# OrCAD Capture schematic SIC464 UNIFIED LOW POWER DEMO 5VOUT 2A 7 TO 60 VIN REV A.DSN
size B; title: SIC464 Demo Low Power Unified Board 7 to 60Vin 5Vout 2A 500K; rev: A
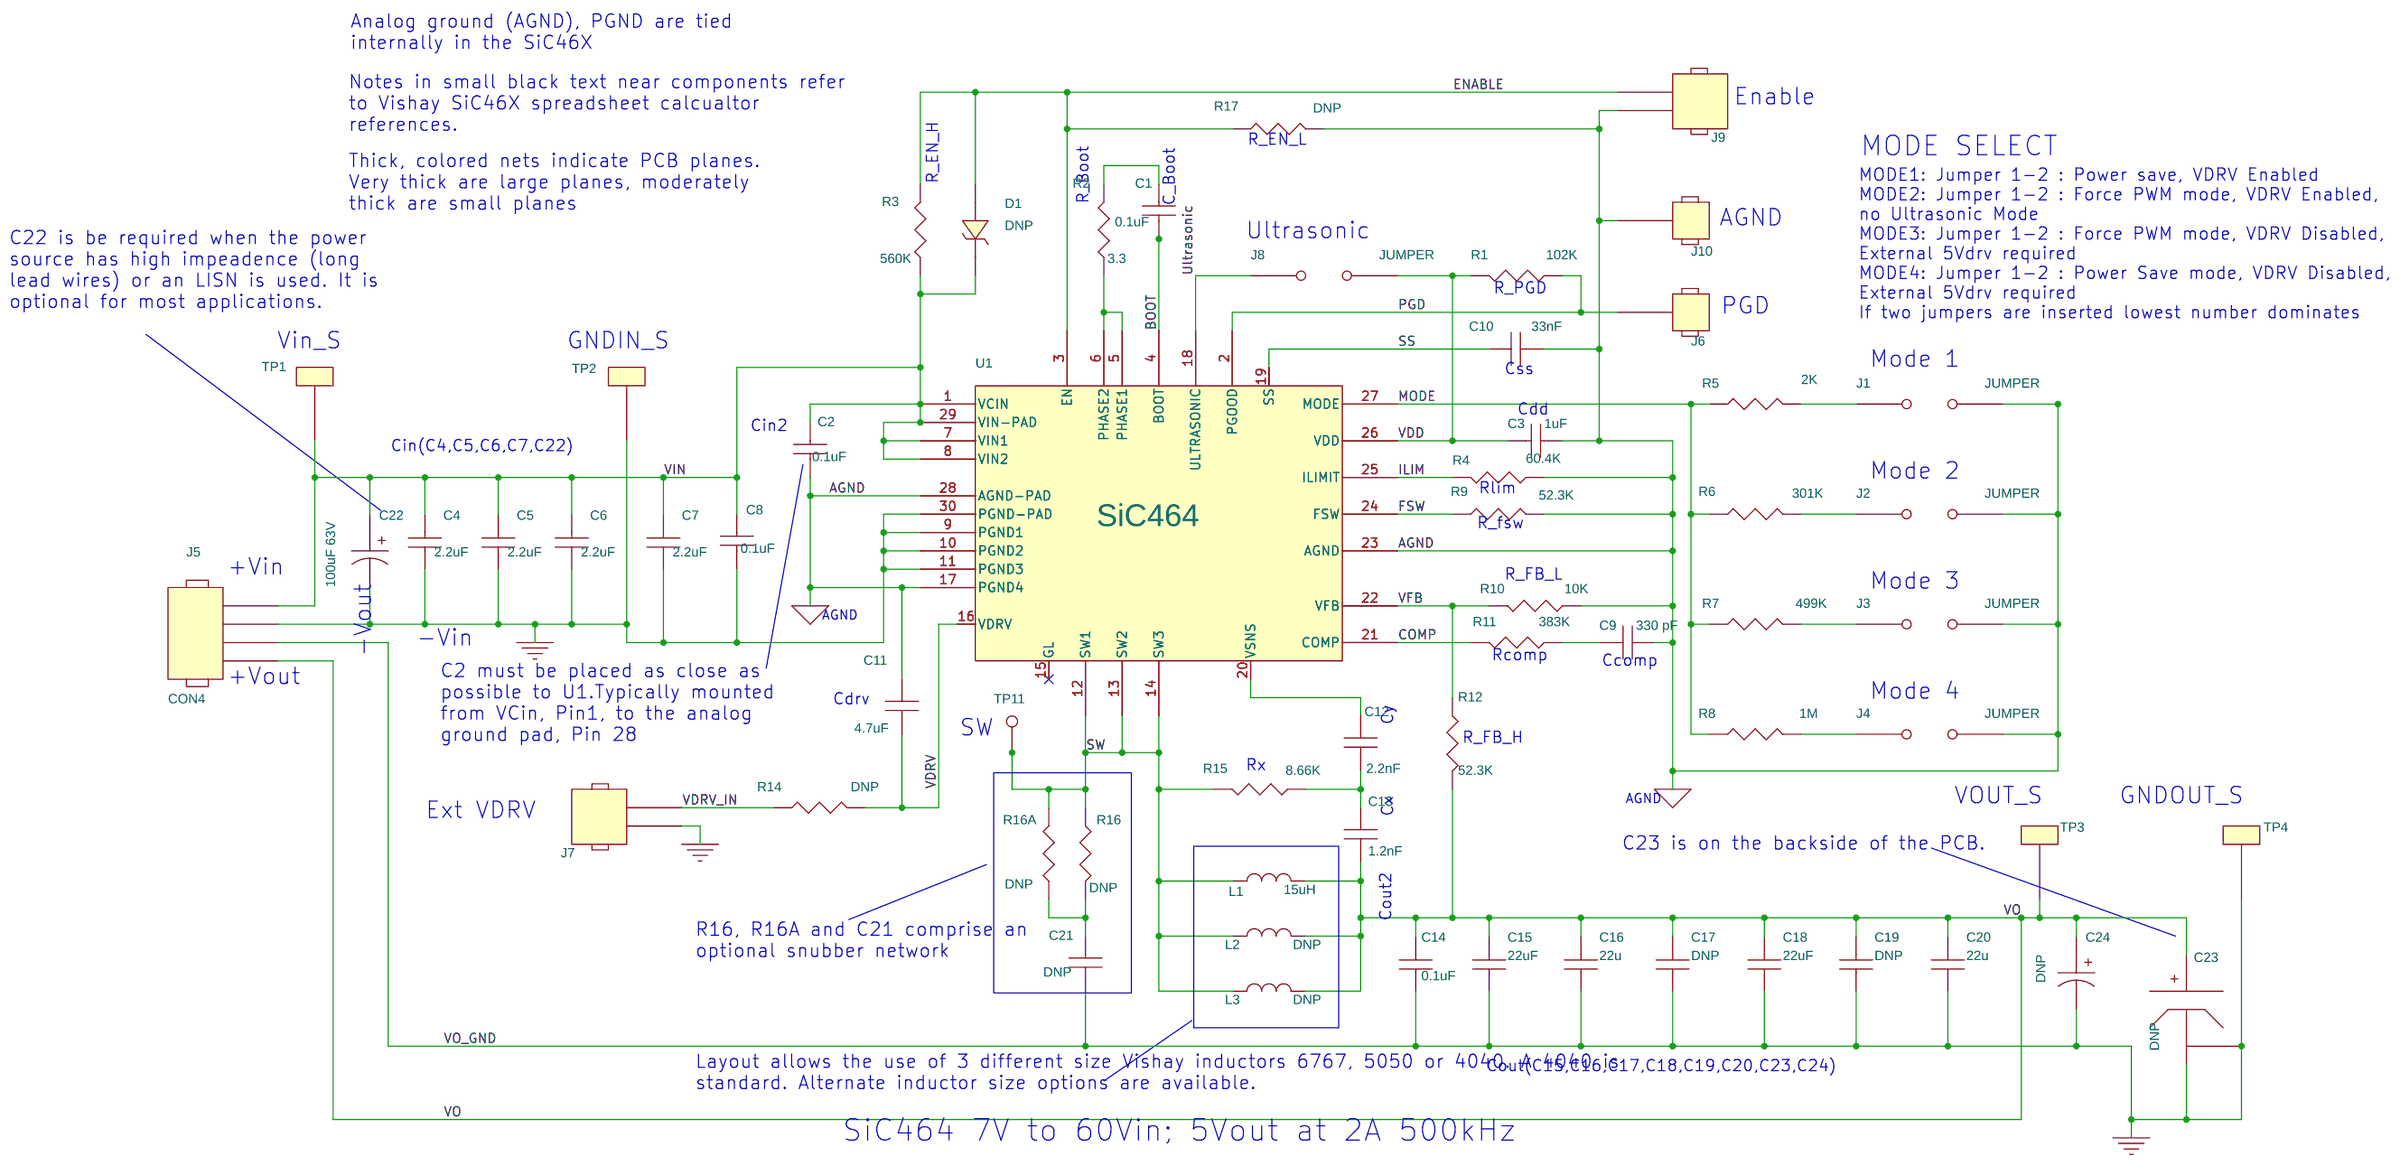
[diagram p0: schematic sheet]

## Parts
C1  0.1uF  [C0603]
C2  0.1uF  [C0603]
C3  1uF  [C0603]
C4  2.2uF  [C1210]
C5  2.2uF  [C1210]
C6  2.2uF  [C1210]
C7  2.2uF  [C1210]
C8  0.1uF  [C0603]
C9  330 pF  [C0603]
C10  33nF  [C0603]
C11  4.7uF  [C0603]
C12  2.2nF  [C0603]
C13  1.2nF  [C0805]
C14  0.1uF  [C0603]
C15  22uF  [C1206]
C16  22u  [C1206]
C17  DNP  [C1206]
C18  22uF  [C1206]
C19  DNP  [C1206]
C20  22u  [C1206]
C21  DNP  [C0603]
C22  100uF 63V
C23  DNP  [T_D27_7343]
C24  DNP
D1  DNP
J1  JUMPER
J2  JUMPER
J3  JUMPER
J4  JUMPER
J5  CON4
J6  PGD  [5002]
J7  EN
J8  JUMPER
J9  EN
J10  GND  [5002]
L1  15uH  [IHLP-4040]
L2  DNP  [IHLP-5050]
L3  DNP  [IHLP-5050]
R1  102K  [R0603]
R2  3.3  [R0603]
R3  560K  [R0603]
R4  60.4K  [R0603]
R5  2K  [R0603]
R6  301K  [R0603]
R7  499K  [R0603]
R8  1M  [R0603]
R9  52.3K  [R0603]
R10  10K  [R0603]
R11  383K  [R0603]
R12  52.3K  [R0603]
R14  DNP  [R0603]
R15  8.66K  [R0805]
R16  DNP  [R0603]
R16A  DNP  [R1210]
R17  DNP  [R0603]
TP1  test point  [5002]
TP2  test point  [5002]
TP3  test point  [5002]
TP4  test point  [5002]
TP11  5002  [PAD040_060_SQ]
U1  SiC464  [5mmx5mm]

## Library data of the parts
C1 C2 C8 = CAP_NP: Ceramic Cap, 0.1uF,100volts X7R,10%,0603; DIGI-KEY: 81-GCM188R72A104KA4D; Data sheet\: http://www.mouser.com/ds/2/281/c03e-806517.pdf; Description1: Ceramic Cap, 0.1uF,100volts, X7R, 10%, 0603; Description2: Ceramic Cap, 0.1uF,100volts, X7R, 10%, 0603; DigikeyMouser: 81-GCM188R72A104KA4D; Mfr: Murata Electronics; Mfr Part Number: GCM188R72A104KA64D; PCB Footprint1: 0603; PCB Footprint2: 0603; Package: 0603; Package1: 0603; Package2: 0603
C3 = CAP_NP: Ceramic Cap, 1uF,50V, X7R,0603,10%; Comment: X7R; DIGI-KEY: 963-UMK107AB7105KA-T; Data sheet\: http://www.mouser.com/ds/2/396/mlcc11_hq_e-541564.pdf; Description1: Ceramic Cap, 1uF,50V, X7R,0603,10%; Description2: Ceramic Cap, 1uF,50V, X7R,0603,10%; DigikeyMouser: 963-UMK107AB7105KA-T; Manufacturer: Taiyo Yuden; Manufacturer Part: UMK107AB7105KA-T; Manufacturer Part1: UMK107AB7105KA-T; Manufacturer Part2: UMK107AB7105KA-T; Manufacturer1: Taiyo Yuden; Manufacturer2: Taiyo Yuden; Mfr: Taiyo Yuden; Mfr Part Number: UMK107AB7105KA-T; Package: 0603; Package1: 0603; Package2: 0603; Tolerance: 10%; Voltage: 50V
C4-C7 = CAP_NP: Ceramic Cap, 2.2uF,100volts, X7R, 10%, 1210; DIGI-KEY: 81-GRM32ER72A225KA5K; Data sheet\: http://www.mouser.com/ds/2/281/c02e-2905.pdf; Description1: Ceramic Cap, 2.2uF,100volts, X7R, 10%, 1210; Description2: Ceramic Cap, 2.2uF,100volts, X7R, 10%, 1210; DigikeyMouser: 81-GRM32ER72A225KA5K; Mfr: Murata Electronics; Mfr Part Number: GRM32ER72A225KA35K
C9 = CAP_NP: Ceramic Cap, 330pF,50V,C0G,0603,5%; Comment: C0G; DIGI-KEY: 77-VJ0603A331JXAAC; Data sheet\: http://www.mouser.com/ds/2/427/vjcommercialseries-222796.pdf; Description1: Ceramic Cap, 330pF,50V,C0G,0603,5%; Description2: Ceramic Cap, 330pF,50V,C0G,0603,5%; DigikeyMouser: 77-VJ0603A331JXAAC; Manufacturer: Vishay; Manufacturer Part: VJ0603A331JXAAC; Manufacturer Part1: VJ0603A331JXAAC; Manufacturer Part2: VJ0603A331JXAAC; Manufacturer1: Vishay; Manufacturer2: Vishay; Mfr: Vishay; Mfr Part Number: VJ0603A331JXAAC; Package: 0603; Package1: 0603; Package2: 0603; Tolerance: 5%; Voltage: 50V
C10 = CAP_NP: Ceramic Cap, 0.033uF,50V,X7R,0603,10%; Comment: X7R; DIGI-KEY: 77-VJ0603Y333KXACBC; Data sheet\: http://www.mouser.com/ds/2/427/vjw1bcbascomseries-223529.pdf; Description1: Ceramic Cap, 0.033uF,50V,X7R,0603,10%; Description2: Ceramic Cap, 0.033uF,50V,X7R,0603,10%; DigikeyMouser: 77-VJ0603Y333KXACBC; Manufacturer: Vishay; Manufacturer Part: VJ0603Y333KXACW1BC; Manufacturer Part1: VJ0603Y333KXACW1BC; Manufacturer Part2: VJ0603Y333KXACW1BC; Manufacturer1: Vishay; Manufacturer2: Vishay; Mfr: Vishay / Vitramon; Mfr Part Number: VJ0603Y333KXACW1BC; Package: 0603; Package1: 0603; Package2: 0603; Tolerance: 10%; Voltage: 50V
C11 = CAP_NP: Ceramic Cap, 4.7uF,25V,X6S,10%,0603; Comment: X6S; DIGI-KEY: 81-GRM188C81E475KE1D; Data sheet\: http://www.mouser.com/ds/2/281/c02e-2905.pdf; Description1: Ceramic Cap, 4.7uF,25V,X6S,10%,0603; Description2: Ceramic Cap, 4.7uF,25V,X6S,10%,0603; DigikeyMouser: 81-GRM188C81E475KE1D; Mfr: Murata; Mfr Part Number: GRM188C81E475KE11D; Tolerance: 10%; Voltage: 25V
C12 = CAP_NP: Ceramic Cap, 2200pF,100V,X7R,0603, 5%; Comment: X7R; DIGI-KEY: 77-VJ0603Y222JXBCBC; Data sheet\: http://www.mouser.com/ds/2/427/vjw1bcbascomseries-223529.pdf; Description1: Ceramic Cap, 2200pF,100V,X7R,0603, 5%; Description2: Ceramic Cap, 2200pF,100V,X7R,0603, 5%; DigikeyMouser: 77-VJ0603Y222JXBCBC; Manufacturer: Vishay; Manufacturer Part: VJ0603Y222JXBCW1BC; Manufacturer Part1: VJ0603Y222JXBCW1BC; Manufacturer Part2: VJ0603Y222JXBCW1BC; Manufacturer1: Vishay; Manufacturer2: Vishay; Mfr: Vishay; Mfr Part Number: VJ0603Y222JXBCW1BC; Package: 0603; Package1: 0603; Package2: 0603; Tolerance: 5%; Voltage: 100V
C13 = CAP_NP: Ceramic Cap, 1.2nF,100V,X7R,0805, 10%; Comment: X7R; DIGI-KEY: 77-VJ0805Y122KXBPBC; Data sheet\: http://www.mouser.com/ds/2/427/vjw1bcbascomseries-223529.pdf; Description1: Ceramic Cap, 1.2nF,100V,X7R,0805, 10%; Description2: Ceramic Cap, 1.2nF,100V,X7R,0805, 10%; DigikeyMouser: 77-VJ0805Y122KXBPBC; Manufacturer: Vishay; Manufacturer Part: VJ0805Y122KXBPW1BC; Manufacturer Part1: VJ0805Y122KXBPW1BC; Manufacturer Part2: VJ0805Y122KXBPW1BC; Manufacturer1: Vishay; Manufacturer2: Vishay; Mfr: Vishay / Vitramon; Mfr Part Number: VJ0805Y122KXBPW1BC; Package: 0805; Package1: 0805; Package2: 0805; Tolerance: 10%; Voltage: 100V
C14 = CAP_NP: Ceramic Cap, 0.1uF,100volts,X7R,10%,0603; Comment: X7S; Data sheet\: http://www.digikey.com/product-detail/en/C1608X7S2A104K080AB/445-5201-2-ND/2116317; Description1: Ceramic Cap, 0.1uF,100volts,X7R,10%,0603; Description2: Ceramic Cap, 0.1uF,100volts,X7R,10%,0603; DigikeyMouser: 445-5201-2-ND; Manufacturer: Vishay; Manufacturer Part: VJ0603Y104KXB; Manufacturer Part1: VJ0603Y104KXB; Manufacturer Part2: VJ0603Y104KXB; Manufacturer1: Vishay; Manufacturer2: Vishay; Mfr: TDK Corporation; Mfr Part Number: C1608X7S2A104K080AB; Package: 0603; Package1: 0603; Package2: 0603; Tolerance: 10%; Voltage: 100V
C15 C18 = CAP_NP: Ceramic Cap, 22uF,25volts,X7R,10%,1206; Comment: X7R; DIGI-KEY: 581-12061C225KAT2A; Data sheet\: http://www.mouser.com/ds/2/40/X7RDielectric-777024.pdf; Description1: Ceramic Cap, 22uF,25volts,X7R,10%,1206; Description2: Ceramic Cap, 22uF,25volts,X7R,10%,1206; DigikeyMouser: 581-12061C225KAT2A; Mfr: AVX Corporation; Mfr Part Number: 12061C225KAT2A; Tolerance: 10%; Voltage: 100V
C16 C17 C19 C20 = CAP_NP: Ceramic Cap, 22uF,25volts,X7R,10%,1206; Comment: X7R; DIGI-KEY: 581-12061C225KAT2A; Data sheet\: http://www.mouser.com/ds/2/40/X7RDielectric-777024.pdf; Description1: Ceramic Cap, 22uF,25volts,X7R,10%,1206; Description2: Ceramic Cap, 22uF,25volts,X7R,10%,1206; DigikeyMouser: 581-12061C225KAT2A; Mfr: AVX Corporation; Mfr Part Number: 12061C225KAT2A; Tolerance: 10%; Value1: 22uF; Value2: 22uF; Voltage: 100V
C21 = CAP_NP: Comment: X7S; Data sheet\: http://www.digikey.com/product-detail/en/C1608X7S2A104K080AB/445-5201-2-ND/2116317; DigikeyMouser: 445-5201-2-ND; Mfr: TDK Corporation; Mfr Part Number: C1608X7S2A104K080AB; Package: 0603; Package1: 0603; Package2: 0603; Tolerance: 10%; Voltage: 100V
C22 C24 = CAP_POL: CAP, alum, 100uF, 63volt, 105C, 10x12, 4khr; DIGI-KEY: 594-2222-150-58101; Data sheet\: http://www.mouser.com/ds/2/427/150rmi-222630.pdf; DigikeyMouser: 594-2222-150-58101; Manufacturer: Vishay; Mfr: Vishay; Mfr Part Number: MAL215058101E3; Part Type: CAP POL; Rating: 63V; Tolerance: 20%
C23 = CAP,_TA-P,V,470u,_2V_0: Polymer SMD 20volts 100uF ESR 55mohm 7343; DIGI-KEY: 667-20TQC100MYF; Data sheet\: http://www.mouser.com/ds/2/315/AAA8000C54-931458.pdf; DigikeyMouser: 667-20TQC100MYF; Mfr: Panasonic; Mfr Part Number: 20TQC100MYF
D1 = DIODE_ZENER: DIGI-KEY: 78-BZX384C3V3-E3-08; Data sheet\: http://www.mouser.com/ds/2/427/bzx384-58924.pdf; DigikeyMouser: 78-BZX384C3V3-E3-08; Mfr: Vishay; Mfr Part Number: BZX384C3V3-E3-08
J1-J4 J8 = JUMPER: BREAKAWAY HDR VERT 2 pitch 100mils; DIGI-KEY: 538-22-28-4023; Data sheet\: http://www.mouser.com/ds/2/276/0022284023_PCB_HEADERS-228360.pdf; Description1: BREAKAWAY HDR VERT 2 pitch 100mils; Description2: BREAKAWAY HDR VERT 2pitch 100mils; DigikeyMouser: 538-22-28-4023; Manufacturer: Molex; Manufacturer Part: 22-28-4023; Manufacturer Part1: 22-28-4023; Manufacturer Part2: 22-28-4023; Manufacturer1: Molex; Manufacturer2: Molex; Mfr: Molex; Mfr Part Number: 22-28-4023
J5 = HEADER_4: TERMINAL BLOCK 3.81MM Horz 4POS; DIGI-KEY: 649-220327-D041B01LF; Data sheet\: http://www.mouser.com/ds/2/18/20020327-941783.pdf; Description1: T; DigikeyMouser: 649-220327-D041B01LF; Man: Amphenol Anytek; Mfr: Amphenol Anytek; Mfr Part Number: 20020327-D041B01LF; Rating: 10A
J6 J10 = HEADER_1: Circuit Board Hardware-PCB TEST POINT WHITE; Description1: Circuit Board Hardware-PCB TEST POINT WHITE; Description2: Circuit Board Hardware-PCB TEST POINT WHITE; Man1: Keystone Electronics; Man2: Keystone Electronics; Manufacturer: Keystone Electronics; Manufacturer1: Keystone Electronics; Manufacturer2: Keystone Electronics
J7 J9 = HEADER_2: BREAKAWAY HDR VERT 2 pitch 100mils; DIGI-KEY: 538-22-28-4023; Data sheet\: http://www.mouser.com/ds/2/276/0022284023_PCB_HEADERS-228360.pdf; Description1: BREAKAWAY HDR VERT 2 pitch 100mils; Description2: BREAKAWAY HDR VERT 2 pitch 100mils; DigikeyMouser: 538-22-28-4023; Manufacturer: Molex; Manufacturer Part: 22-28-4023; Manufacturer Part1: 22-28-4023; Manufacturer Part2: 22-28-4023; Manufacturer1: Molex; Manufacturer2: Molex; Mfr: Molex; Mfr Part Number: 22-28-4023
L1 = IND: INDUCTOR, 15uH,20%,50m DCR,7.7A Saturation; Current: 7.7A; DIGI-KEY: 70-IHLP4040DZR150M5A; Data sheet\: http://www.mouser.com/ds/2/427/ihlp4040dz5a-244384.pdf; Description1: INDUCTOR, 15uH,20%,50m DCR,7.7A Saturation; Description2: INDUCTOR, 15uH,20%,50m DCR,7.7A Saturation; DigikeyMouser: 70-IHLP4040DZR150M5A; Manufacturer: Vishay; Manufacturer Part: IHLP4040DZR150M5A; Manufacturer Part1: IHLP4040DZR150M5A; Manufacturer Part2: IHLP4040DZR150M5A; Manufacturer1: Vishay; Manufacturer2: Vishay; Mfr: Vishay Dale; Mfr Part Number: IHLP4040DZR150M5A; Package1: 4040; Package2: 5050; Value1: 22uH; Value2: 22uH
L2 = IND: INDUCTOR, 15uH,20%,26m DCR,6.8A Saturation; Current: 13A; DIGI-KEY: 70-IHLP5050FDR150M5A; Data sheet\: http://www.mouser.com/ds/2/427/ihlp-5050fd-01-239706.pdf; Description1: INDUCTOR, 15uH,20%,26m DCR,6.8A Saturation; Description2: INDUCTOR, 15uH,20%,26m DCR,6.8A Saturation; DigikeyMouser: 70-IHLP5050FDR150M5A; Manufacturer: Vishay; Manufacturer Part: IHLP5050FDER150M5A; Manufacturer Part1: IHLP5050FDER150M5A; Manufacturer Part2: IHLP5050FDER150M5A; Manufacturer1: Vishay; Manufacturer2: Vishay; Mfr: Vishay Dale; Mfr Part Number: IHLP5050FDER150M5A; Package1: 5050; Package2: 5050; Value1: 15uH; Value2: 15uH
L3 = IND: INDUCTOR, 3.3uH,20%,14m DCR,18.6A Saturation; Current: 8A; Data sheet\: http://www.vishay.com/docs/34193/lp40dz01.pdf; Description1: INDUCTOR, 5.6uH,20%,19m DCR,16A Saturation; Description2: INDUCTOR, 10uH,20%,17.2m DCR,15.5A Saturation; DigikeyMouser: 541-1295-1-ND; Manufacturer: Vishay; Manufacturer Part: IHLP4040DZER3R3M11; Manufacturer Part1: IHLP6767GZER150M5A; Manufacturer Part2: IHLP5050FDER100M01; Manufacturer1: Vishay; Manufacturer2: Vishay; Mfr: Vishay Dale; Mfr Part Number: IHLP4040DZER100M01; Package1: 4040; Package2: 5050; Value1: 5.6uH; Value2: 10uH
R1 = RESISTOR: SMD,102K,1%,0603; DIGI-KEY: 71-CRCW0603-102K-E3; Data sheet\: http://www.mouser.com/ds/2/427/dcrcwe3-109170.pdf; Description1: SMD,102K,1%,0603; Description2: SMD,102K,1%,0603; DigikeyMouser: 71-CRCW0603-102K-E3; Man: Vishay; Man Part Number: CRCW0603102KFKEA; Man Part Number1: CRCW0603102KFKEA; Man Part Number2: CRCW0603102KFKEA; Man1: Vishay; Man2: Vishay; Manufacturer: Vishay; Manufacturer Part: CRCW0603102KFKEA; Manufacturer Part1: CRCW0603102KFKEA; Manufacturer Part2: CRCW0603102KFKEA; Manufacturer1: Vishay; Manufacturer2: Vishay; Mfr: Vishay; Mfr Part Number: CRCW0603102KFKEA; PCB Footprint1: 0603; PCB Footprint2: 0603; Package: 0603; Package1: 0603; Package2: 0603
R2 = RESISTOR: SMD,3.3Ohm, 1% 0603; DIGI-KEY: 71-CRCW06033R30FKEA; Data sheet\: http://www.mouser.com/ds/2/427/dcrcwe3-109170.pdf; Description1: SMD,3.3Ohm, 1% 0603; Description2: SMD,3.3Ohm, 1% 0603; DigikeyMouser: 71-CRCW06033R30FKEA; Man: Vishay; Man Part Number: CRCW06033R30FKEA; Man Part Number1: CRCW06033R30FKEA; Man Part Number2: CRCW06033R30FKEA; Man1: Vishay; Man2: Vishay; Manufacturer: Vishay; Manufacturer Part: CRCW06030000ZSTA; Manufacturer Part1: CRCW06030000ZSTA; Manufacturer Part2: CRCW06030000ZSTA; Manufacturer1: Vishay; Manufacturer2: Vishay; Mfr: Vishay; Mfr Part Number: CRCW06033R30FKEA; PCB Footprint1: 0603; PCB Footprint2: 0603; Package: 0603; Package1: 0603; Package2: 0603
R3 = RESISTOR: SMD,560K,1%,0603; DIGI-KEY: 71-CRCW0603-560K-E3; Data sheet\: http://www.mouser.com/ds/2/427/dcrcwe3-109170.pdf; Description1: SMD,560K,1%,0603; Description2: SMD,560K,1%,0603; DigikeyMouser: 71-CRCW0603-560K-E3; Man: Vishay; Man Part Number: CRCW0603560KFKEA; Man Part Number1: CRCW0603560KFKEA; Man Part Number2: CRCW0603560KFKEA; Man1: Vishay; Man2: Vishay; Manufacturer: Vishay; Manufacturer Part: CRCW0603560KFKTA; Manufacturer Part1: CRCW0603560KFKTA; Manufacturer Part2: CRCW0603560KFKTA; Manufacturer1: Vishay; Manufacturer2: Vishay; Mfr: Vishay; Mfr Part Number: CRCW0603560KFKEA; PCB Footprint1: 0603; PCB Footprint2: 0603; Package: 0603; Package1: 0603; Package2: 0603
R4 = RESISTOR: SMD,60.4k,1%,0603; DIGI-KEY: 71-CRCW0603-60.4K-E3; Data sheet\: http://www.digikey.com/product-detail/en/vishay-dale/CRCW04024K64FKED/541-4.64KLCT-ND/1183198; Description1: SMD,60.4K,1%,0603; Description2: SMD,60.4K,1%,0603; DigikeyMouser: 71-CRCW0603-60.4K-E3; Manufacturer: Vishay; Manufacturer Part: CRCW060360K4FKEA; Manufacturer Part1: CRCW060360K4FKEA; Manufacturer Part2: CRCW060360K4FKEA; Manufacturer1: Vishay; Manufacturer2: Vishay; Mfr: Vishay Dale; Mfr Part Number: CRCW060360K4FKEA; Package: 0603; Package1: 0603; Package2: 0603; Tolerance: 1%; Value1: 60.4k; Value2: 60.4k
R5 = RESISTOR: SMD,2K,1%,0603; DIGI-KEY: 71-CRCW06032K00FKEB; Data sheet\: http://www.mouser.com/ds/2/427/dcrcwe3-109170.pdf; Description1: SMD,2K,1%,0603; Description2: SMD,2K,1%,0603; DigikeyMouser: 71-CRCW06032K00FKEB; Manufacturer: Vishay; Manufacturer Part: CRCW06032K00FKEB; Manufacturer Part1: CRCW06032K00FKEB; Manufacturer Part2: CRCW06032K00FKEB; Manufacturer1: Vishay; Manufacturer2: Vishay; Mfr: Vishay Dale; Mfr Part Number: CRCW06032K00FKEB; Package: 0603; Package1: 0603; Package2: 0603; Tolerance: 1%
R6 = RESISTOR: SMD,301K,1%,0603; DIGI-KEY: 71-CRCW0603-301K-E3; Data sheet\: http://www.mouser.com/ds/2/427/dcrcwe3-109170.pdf; Description1: SMD,301K,1%,0603; Description2: SMD,301K,1%,0603; DigikeyMouser: 71-CRCW0603-301K-E3; Manufacturer: Vishay; Manufacturer Part: CRCW0603301KFKEA; Manufacturer Part1: CRCW0603301KFKEA; Manufacturer Part2: CRCW0603301KFKEA; Manufacturer1: Vishay; Manufacturer2: Vishay; Mfr: Vishay Dale; Mfr Part Number: CRCW0603301KFKEA; Package: 0603; Package1: 0603; Package2: 0603; Tolerance: 1%
R7 = RESISTOR: SMD,499K,1%,0603; DIGI-KEY: 71-CRCW0603-499K-E3; Data sheet\: http://www.mouser.com/ds/2/427/dcrcwe3-109170.pdf; Description1: SMD,499K,1%,0603; Description2: SMD,499K,1%,0603; DigikeyMouser: 71-CRCW0603-499K-E3; Manufacturer: Vishay; Manufacturer Part: CRCW0603499KFKEA; Manufacturer Part1: CRCW0603499KFKEA; Manufacturer Part2: CRCW0603499KFKEA; Manufacturer1: Vishay; Manufacturer2: Vishay; Mfr: Vishay Dale; Mfr Part Number: CRCW0603499KFKEA; Package: 0603; Package1: 0603; Package2: 0603; Tolerance: 1%
R8 = RESISTOR: SMD,1000K,1%,0603; DIGI-KEY: 71-RCG06031M00FKEA; Data sheet\: http://www.mouser.com/ds/2/427/rcge3-254226.pdf; Description1: SMD,1000K,1%,0603; Description2: SMD,1000K,1%,0603; DigikeyMouser: 71-RCG06031M00FKEA; Manufacturer: Vishay; Manufacturer Part: RCG06031M00FKEA; Manufacturer Part1: RCG06031M00FKEA; Manufacturer Part2: RCG06031M00FKEA; Manufacturer1: Vishay; Manufacturer2: Vishay; Mfr: Vishay Dale; Mfr Part Number: RCG06031M00FKEA; Package: 0603; Package1: 0603; Package2: 0603; Tolerance: 1%
R9 = RESISTOR: SMD 1,10W 52.3K Ohms 1%; DIGI-KEY: 71-CRCW0603-52.3K-E3; Data sheet\: http://www.mouser.com/ds/2/427/dcrcwe3-109170.pdf; Description1: SMD 1,10W 52.3K Ohms 1%; Description2: SMD 1,10W 52.3K Ohms 1%; DigikeyMouser: 71-CRCW0603-52.3K-E3; Manufacturer: Vishay; Manufacturer Part: CRCW060352K3FKEA; Manufacturer Part1: CRCW060352K3FKEA; Manufacturer Part2: CRCW060352K3FKEA; Manufacturer1: Vishay; Manufacturer2: Vishay; Mfr: Vishay Dale; Mfr Part Number: CRCW060352K3FKEA; Package: 0603; Package1: 0603; Package2: 0603; Tolerance: 1%
R10 = RESISTOR: SMD,10K,1%,0603; DIGI-KEY: 71-CRCW0603-10K; Data sheet\: http://www.mouser.com/ds/2/427/dcrcwe3-109170.pdf; Description1: SMD,10K,1%,0603; Description2: SMD,10K,1%,0603; DigikeyMouser: 71-CRCW0603-10K; Manufacturer: Vishay; Manufacturer Part: CRCW060310K0FKTA; Manufacturer Part1: CRCW060310K0FKTA; Manufacturer Part2: CRCW060310K0FKTA; Manufacturer1: Vishay; Manufacturer2: Vishay; Mfr: Vishay Dale; Mfr Part Number: CRCW060310K0FKTA; Package: 0603; Package1: 0603; Package2: 0603; Tolerance: 1%
R11 = RESISTOR: SMD 1/10watt 383Kohms 1%,0603; DIGI-KEY: 71-CRCW0603-383K-E3; Data sheet\: http://www.mouser.com/ds/2/427/dcrcwe3-109170.pdf; Description1: SMD 1/10watt 383Kohms 1%,0603; Description2: SMD 1/10watt 383Kohms 1%,0603; DigikeyMouser: 71-CRCW0603-383K-E3; Manufacturer: Vishay; Manufacturer Part: CRCW0603383KFKEA; Manufacturer Part1: CRCW0603383KFKEA; Manufacturer Part2: CRCW0603383KFKEA; Manufacturer1: Vishay; Manufacturer2: Vishay; Mfr: Vishay Dale; Mfr Part Number: CRCW0603383KFKEA; Package: 0603; Package1: 0603; Package2: 0603; Tolerance: 1%
R12 = RESISTOR: SMD 1,10W 52.3 kOhms 1% 0603; DIGI-KEY: 71-CRCW0603-52.3K-E3; Data sheet\: http://www.mouser.com/ds/2/427/dcrcwe3-109170.pdf; Description1: SMD 1,10W 52.3 kOhms 1% 0603; Description2: SMD 1,10W 52.3 kOhms 1% 0603; DigikeyMouser: 71-CRCW0603-52.3K-E3; Manufacturer: Vishay; Manufacturer Part: CRCW060352K3FKEA; Manufacturer Part1: CRCW060352K3FKEA; Manufacturer Part2: CRCW060352K3FKEA; Manufacturer1: Vishay; Manufacturer2: Vishay; Mfr: Vishay Dale; Mfr Part Number: CRCW060352K3FKEA; Package: 0603; Package1: 0603; Package2: 0603; Tolerance: 1%
R14 R16 = RESISTOR: Data sheet\: http://www.digikey.com/product-detail/en/vishay-dale/CRCW04024K64FKED/541-4.64KLCT-ND/1183198; DigikeyMouser: 541-4.64KLCT-ND; Mfr: Vishay Dale; Mfr Part Number: CRCW04024K64FKED; Package: 0603; Package1: 0603; Package2: 0603; Tolerance: 1%
R15 = RESISTOR: Resistors - SMD 1/8watt 8.66Kohms 1% 0805; DIGI-KEY: 71-CRCW0805-8.66K-E3; Data sheet\: http://www.mouser.com/ds/2/427/dcrcw-72725.pdf; Description1: Resistors - SMD 1/8watt 8.66Kohms 1% 0805; Description2: Resistors - SMD 1/8watt 8.66Kohms 1% 0805; DigikeyMouser: 71-CRCW0805-8.66K-E3; Mfr: Vishay Dale; Mfr Part Number: CRCW08058K66FKEA; Tolerance: 1%
R16A = RESISTOR: SMD,1.0K,1%,1210; DIGI-KEY: 71-CRCW12101K00FKEAH; Data sheet\: http://www.mouser.com/ds/2/427/crcwhpe3-46056.pdf; DigikeyMouser: 71-CRCW12101K00FKEAH; Manufacturer: Vishay; Manufacturer Part: CRCW12101K00FKEAHP; Mfr: Vishay Dale; Mfr Part Number: CRCW12101K00FKEAHP; Package: 1210; Tolerance: 1%
R17 = RESISTOR: Package: 0603; Package1: 0603; Package2: 0603
TP1-TP4 = TEST_POINT: Circuit Board Hardware-PCB TEST POINT WHITE; Description1: Circuit Board Hardware-PCB TEST POINT WHITE; Description2: Circuit Board Hardware-PCB TEST POINT WHITE; Man: Keystone Electronics; Man Part Number1: Keystone Electronics 5002; Man Part Number2: Keystone Electronics 5002; Man1: Keystone Electronics; Man2: Keystone Electronics; Manufacturer: Keystone Electronics; Manufacturer1: Keystone Electronics; Manufacturer2: Keystone Electronics
TP11 = TP_0: TST PNT,WHT INSL,0.050"ID; DIGI-KEY: 5002K-ND; Mfr: KEYSTONE ELECTRONICS CORP.; Part Type: TP
U1 = SiC462CD-T1-GE3_33: 4.5~60V, 2A, High Voltage microBuck; DIGI-KEY: 78-SIC464ED-T1-GE3; Data sheet\: http://www.mouser.com/ds/2/427/sic462-1061838.pdf; Description1: 4.5~60V, 2A, High Voltage microBuck; Description2: 4.5~60V, 2A, High Voltage microBuck; DigikeyMouser: 78-SIC464ED-T1-GE3; Man: Vishay; Man Part Number: SIC464CD-T1-GE3; Man Part Number1: SIC464CD-T1-GE3; Man Part Number2: SIC464CD-T1-GE3; Man1: Vishay; Man2: Vishay; Mfr: Vishay; Mfr Part Number: SIC464ED-T1-GE3

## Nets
GND: C4.1 C5.1 C6.1 C7.1 C8.2 C14.1 C15.1 C16.1 C17.1 C18.1 C19.1 C20.1 C21.2 C22.2 C23.2 C23.3 C24.2 J5.2 J5.3 J7.2 TP2.1 TP4.1 U1.9(PGND1) U1.10(PGND2) U1.11(PGND3) U1.30(PGND-PAD)
GND_SIGNAL: C2.2 C3.1 C9.1 C10.2 C11.1 J1.1 J2.1 J3.1 J4.1 J9.2 J10.1 R4.1 R9.2 R10.1 R17.1 U1.17(PGND4) U1.23(AGND) U1.28(AGND-PAD)
VDD: C3.2 J8.1 R1.2 U1.26(VDD)
VIN: C2.1 C4.2 C5.2 C6.2 C7.2 C8.1 C22.1 D1.1(CATHODE) J5.1 R3.1 TP1.1 U1.1(VCIN) U1.7(VIN1) U1.8(VIN2) U1.29(VIN-PAD)
BOOT: C1.2 U1.4(BOOT)
COMP: R11.2 U1.21(COMP)
ENABLE: D1.2(ANODE) J9.1 R3.2 R17.2 U1.3(EN)
FSW: R9.1 U1.24(FSW)
ILIM: R4.2 U1.25(ILIMIT)
MODE: R5.1 R6.1 R7.1 R8.1 U1.27(MODE)
PGD: J6.1 R1.1 U1.2(PGOOD)
SS: C10.1 U1.19(SS)
SW: L1.2(B) L2.2(B) L3.2(B) R15.2 R16.1 R16A.1 TP11.1 U1.12(SW1) U1.13(SW2) U1.14(SW3)
Ultrasonic: J8.2 U1.18(ULTRASONIC)
VDRV: C11.2 R14.2 U1.16(VDRV)
VDRV_IN: J7.1 R14.1
VFB: R10.2 R12.1 U1.22(VFB)
VO: C13.2 C14.2 C15.2 C16.2 C17.2 C18.2 C19.2 C20.2 C23.1 C24.1 J5.4 L1.1(A) L2.1(A) L3.1(A) R12.2 TP3.1
N16770186: R2.1 U1.5(PHASE1) U1.6(PHASE2)
N16770229: C1.1 R2.2
N16771868: C9.2 R11.1
N16772198: J1.2 R5.2
N16772202: J2.2 R6.2
N16772206: J3.2 R7.2
N16812890: C21.1 R16.2 R16A.2
N16829136: J4.2 R8.2
N16842327: C12.1 U1.20(VSNS)
N16874863: C12.2 C13.1 R15.1

Not connected (* = marked no-connect by the designer): U1 15(GL)*

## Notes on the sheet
- Analog ground (AGND), PGND are tied
  internally in the SiC46X
- Notes in small black text near components refer
  to Vishay SiC46X spreadsheet calcualtor
  references.
- Enable
- R_EN_L
- Thick, colored nets indicate PCB planes.
  Very thick are large planes, moderately
  thick are small planes
- MODE SELECT
- MODE1: Jumper 1-2 : Power save, VDRV Enabled
  MODE2: Jumper 1-2 : Force PWM mode, VDRV Enabled,
  no Ultrasonic Mode
  MODE3: Jumper 1-2 : Force PWM mode, VDRV Disabled,
  External 5Vdrv required
  MODE4: Jumper 1-2 : Power Save mode, VDRV Disabled,
  External 5Vdrv required
  If two jumpers are inserted lowest number dominates
- R_EN_H
- R_Boot
- C_Boot
- Ultrasonic
- AGND
- C22 is be required when the power
  source has high impeadence (long
  lead wires) or an LISN is used. It is
  optional for most applications.
- R_PGD
- PGD
- Vin_S
- GNDIN_S
- Mode 1
- Css
- Cdd
- Cin2
- Cin(C4,C5,C6,C7,C22)
- Mode 2
- Rlim
- R_fsw
- +Vin
- R_FB_L
- Mode 3
- AGND
- -Vin
- Rcomp
- Ccomp
- +Vout
- -Vout
- C2 must be placed as close as
  possible to U1.Typically mounted
  from VCin, Pin1, to the analog
  ground pad, Pin 28
- Cdrv
- Mode 4
- SW
- Cy
- R_FB_H
- Rx
- Ext VDRV
- AGND
- VOUT_S
- GNDOUT_S
- Cx
- C23 is on the backside of the PCB.
- R16, R16A and C21 comprise an
  optional snubber network
- Cout2
- Layout allows the use of 3 different size Vishay inductors 6767, 5050 or 4040. A 4040 is
  standard. Alternate inductor size options are available.
- Cout(C15,C16,C17,C18,C19,C20,C23,C24)
- SiC464 7V to 60Vin; 5Vout at 2A 500kHz
